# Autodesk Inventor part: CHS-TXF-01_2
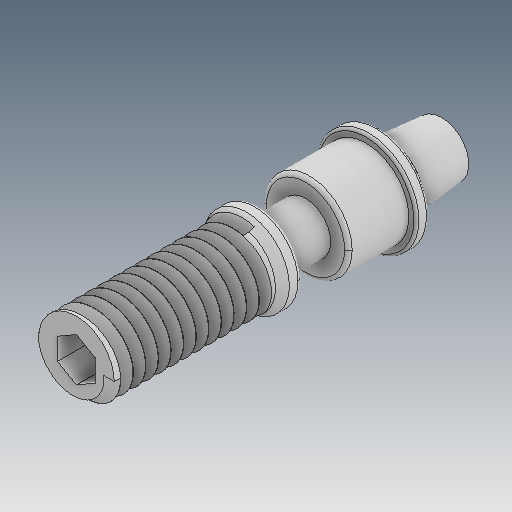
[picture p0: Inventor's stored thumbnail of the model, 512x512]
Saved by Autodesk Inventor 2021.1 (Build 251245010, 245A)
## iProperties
Created: 2019-05
Part Number: CHS-TXF-01_2
Material: Ogólny
Document SubType Name: Modeling
Designer: user
Density: 1 g/cm^3
Appearance: Domyślna
Author: user
Revision Number: ÈÎºÎ
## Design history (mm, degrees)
feature "ÊäÈë1"
node "Bryła1"
